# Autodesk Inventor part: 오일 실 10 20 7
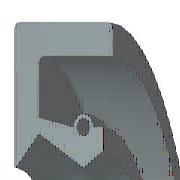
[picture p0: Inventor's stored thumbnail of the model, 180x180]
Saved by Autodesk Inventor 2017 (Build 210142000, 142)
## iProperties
IsCustomPart: 1
Created: 2012-02
Part Number: 오일 실 10 20 7
Material: 고무
Description: 오일-실
Document SubType Name: Modeling
Standard: KS B 2804
Designer: mduedu
Standards Organization: KS
Language: ko-KR
Size Designation: D - 10 20 7
Categories: <MemberInstance><Categories><Category DisplayName="샤프트 부품" InternalName="7f7aeb1f-a693-4053-b835-cee3144e0d98" Mnemonic="SHFT"><Category DisplayName="실링" Intern
Density: 0.93 g/cm^3
Appearance: 고무 - 검은색 - 버전 1.1
Author: mduedu
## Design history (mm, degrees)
revolve "본체" stored, may be unused: angle "d17" = 90 deg
revolve "스프링1" stored, may be unused: angle "d18" = 90 deg
body "Solid1"
sketch "스케치1"
  geometry: L1 (0, 10)-(7, 10); L2 (7, 8.25)-(1.75, 8.25); L3 (1.75, 6.75)-(4.9, 5); L4 (4.9, 5)-(0, 5); L5 (0, 0)-(9.586, 0) reference; L6 (4.9, 5)-(6.3, 5.875); L7 (0, 18)-(0, -3) reference; L8 (-1.941, 0)-(11.507, 0) reference; L9 (4.2, 7.1)-(1.75, 7.59); L10 (1.75, 7.59)-(1.75, 8.25); L11 (0, 10)-(0, 5.088); L12 (4.9, 5)-(0, 5); L13 (1.75, 6.75)-(0.152, 5.028); L14 (7, 10)-(7, 8.25); L15 (5.6, 7.1)-(6.3, 7.1); L16 (6.3, 7.1)-(6.3, 5.875); C1 r 0.455 at (4.9, 7.1); A1 r 0.7 centre (4.9, 7.1) between (5.6, 7.1) and (4.2, 7.1); A2 r 0.088 centre (0.088, 5.088) between (0, 5.088) and (0.152, 5.028); 1 further point
  constraints: 28 end point, 5 horizontal alignment, 5 point on line, 4 point on circle, 4 vertical alignment, 3 centre point, 3 tangent, 2 collinear, 2 horizontal, 2 perpendicular, 1 coincident, 1 parallel
  dimensions: "d0" = 20 diameter of L1 L5 (= SD2); "d1" = 1.75 distance of L1.end L2.start (= SD); "d2" = 0.91 diameter of C1 (= SPDI); "d3" = 1.4 diameter of A1 (= SPDA); "d4" = 10 diameter of L3.end L5 (= NND); "d5" = 13.5 diameter of L3.start L5 (= TKDM); "d7" = 15.18 diameter of L9.end L5 (= TKDM + 0.24 x SWDT); "d8" = 1.75 distance between parallel lines of L11 L10 (= SD); "d9" = 4.9 distance from line of L11 C1.centre (= SPDST); "d10" = 14.2 diameter of C1.centre L5 (= HLDM); "d11" = 0.0875 radius of A2 (= 0.25 x LAB); "d12" = 6.3 distance between parallel lines of L11 L16 (= SDI); "d13" = 11.75 diameter of L6.end L5 (= ABDM); "d14" = 7 distance from line of L11 L1.end (= SWDT)
fillet "모깎기1" dims "d6" = 0.3 (= RR)
other parameters: "SD2" = 20 [user parameter; used in 1 equation term], "SWDT" = 7 [user parameter; used in 2 equation terms], "RR" = 0.3 [user parameter; used in 1 equation term], "SD" = 1.75 [user parameter; used in 2 equation terms], "NND" = 10 [user parameter; used in 1 equation term], "SPDA" = 1.4 [user parameter; used in 1 equation term], "SPDI" = 0.91 [user parameter; used in 1 equation term], "TKDM" = 13.5 [user parameter; used in 2 equation terms], "HLDM" = 14.2 [user parameter; used in 1 equation term], "ABDM" = 11.75 [user parameter; used in 1 equation term], "SDI" = 6.3 [user parameter; used in 1 equation term], "SPDST" = 4.9 [user parameter; used in 1 equation term], "LAB" = 0.35 [user parameter; used in 1 equation term], "d15" = 0, "d16" = 0, "d19" = 0
